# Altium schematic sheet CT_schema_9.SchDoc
size 287 x 160 mm
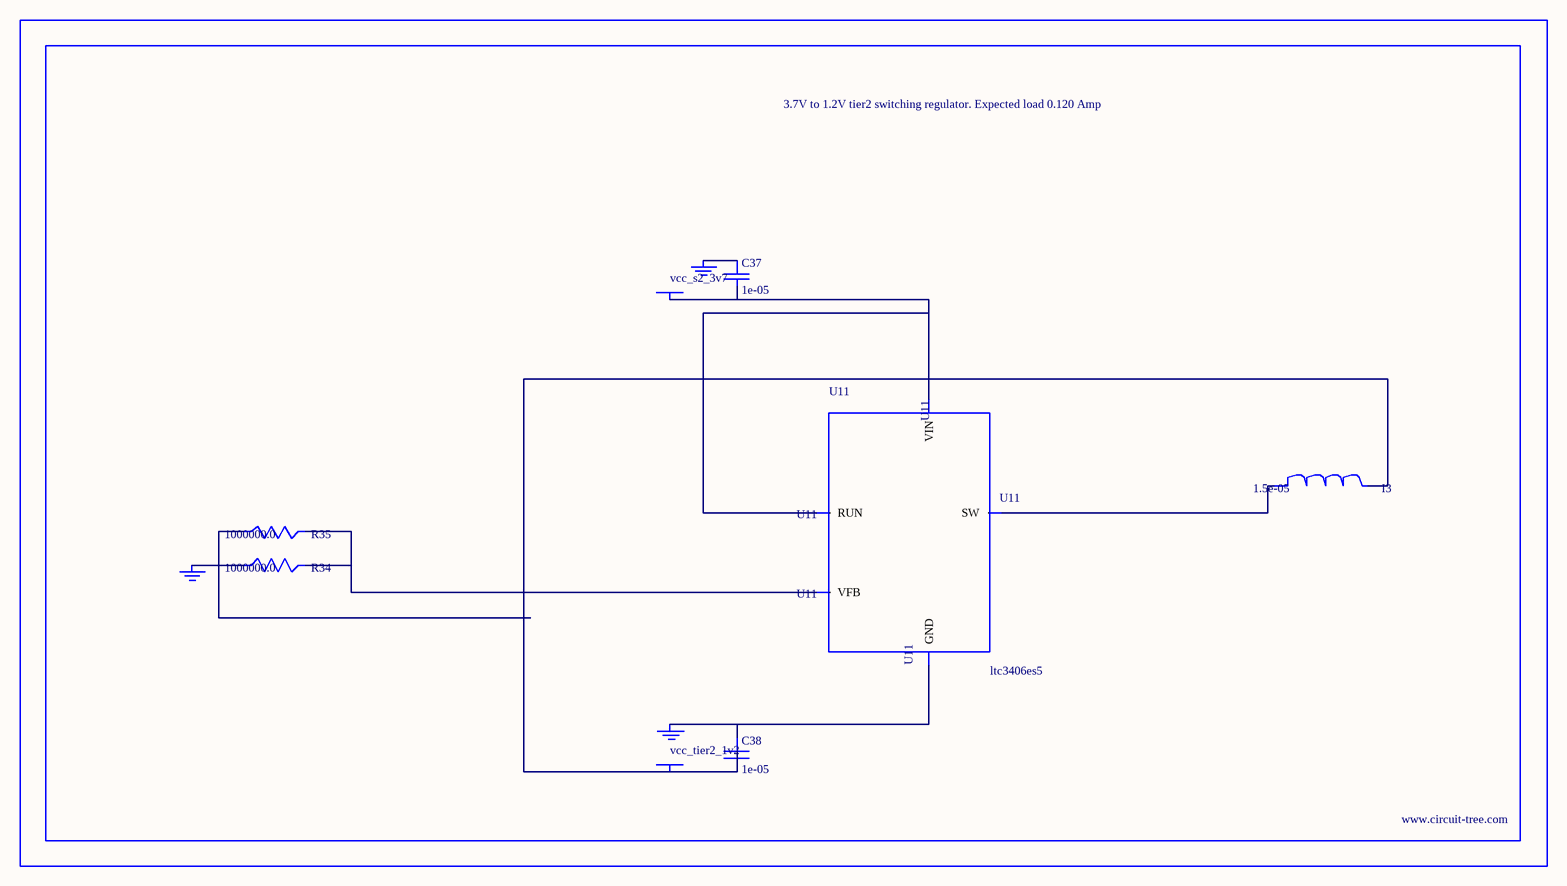
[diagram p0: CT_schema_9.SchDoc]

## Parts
BORDER8  (no value)
C37  1e-05  [C0805]
C38  1e-05  [C0805]
GND_INSTANCE_8_0  (no value)
GND_INSTANCE_8_1  (no value)
GND_INSTANCE_8_2  (no value)
I3  1.5e-05  [L1210]
POWER_INSTANCE_8_0  vcc_tier2_1v2
POWER_INSTANCE_8_1  vcc_s2_3v7
R34  1000000.0  [R0603]
R35  1000000.0  [R0603]
U11  ltc3406es5  [TSOT-23-5]

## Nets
NetC37_1: C37.1 GND_INSTANCE_8_1.0(GND)
NetC37_2: C37.2 POWER_INSTANCE_8_1.0(PWR) U11.1(RUN) U11.4(VIN)
NetC38_1: C38.1 GND_INSTANCE_8_0.0(GND) U11.2(GND)
NetC38_2: C38.2 I3.2 POWER_INSTANCE_8_0.0(PWR) R35.1
NetGND_INSTANCE_8_2_0: GND_INSTANCE_8_2.0(GND) R34.1
NetI3_1: I3.1 U11.3(SW)
NetR34_2: R34.2 R35.2 U11.5(VFB)

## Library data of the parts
BORDER8 = BORDER_PAGE8
C37 C38 = C0805C106K8RACTU
GND_INSTANCE_8_0-GND_INSTANCE_8_2 = GND
I3 = L1210R150MDWIT
POWER_INSTANCE_8_0 POWER_INSTANCE_8_1 = PWR
R34 R35 = RC0603JR-071ML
